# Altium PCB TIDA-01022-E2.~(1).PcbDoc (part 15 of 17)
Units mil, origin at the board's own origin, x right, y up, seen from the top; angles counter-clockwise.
Board outline 6929.13 x 11614.17 mil, 12 copper layers (L1_Top Layer, L2_GND, L3_GND, L4_Signal Layer 1, L5_GND, L6_PWR, L7_GND/PWR, L8_PWR, L9_GND/PWR, L10_Signal Layer 2, L11_GND, L12_Bottom Layer), stack 64.6 mil thick; 1711 components, 1001 nets, 5985 pads, 3200 vias.
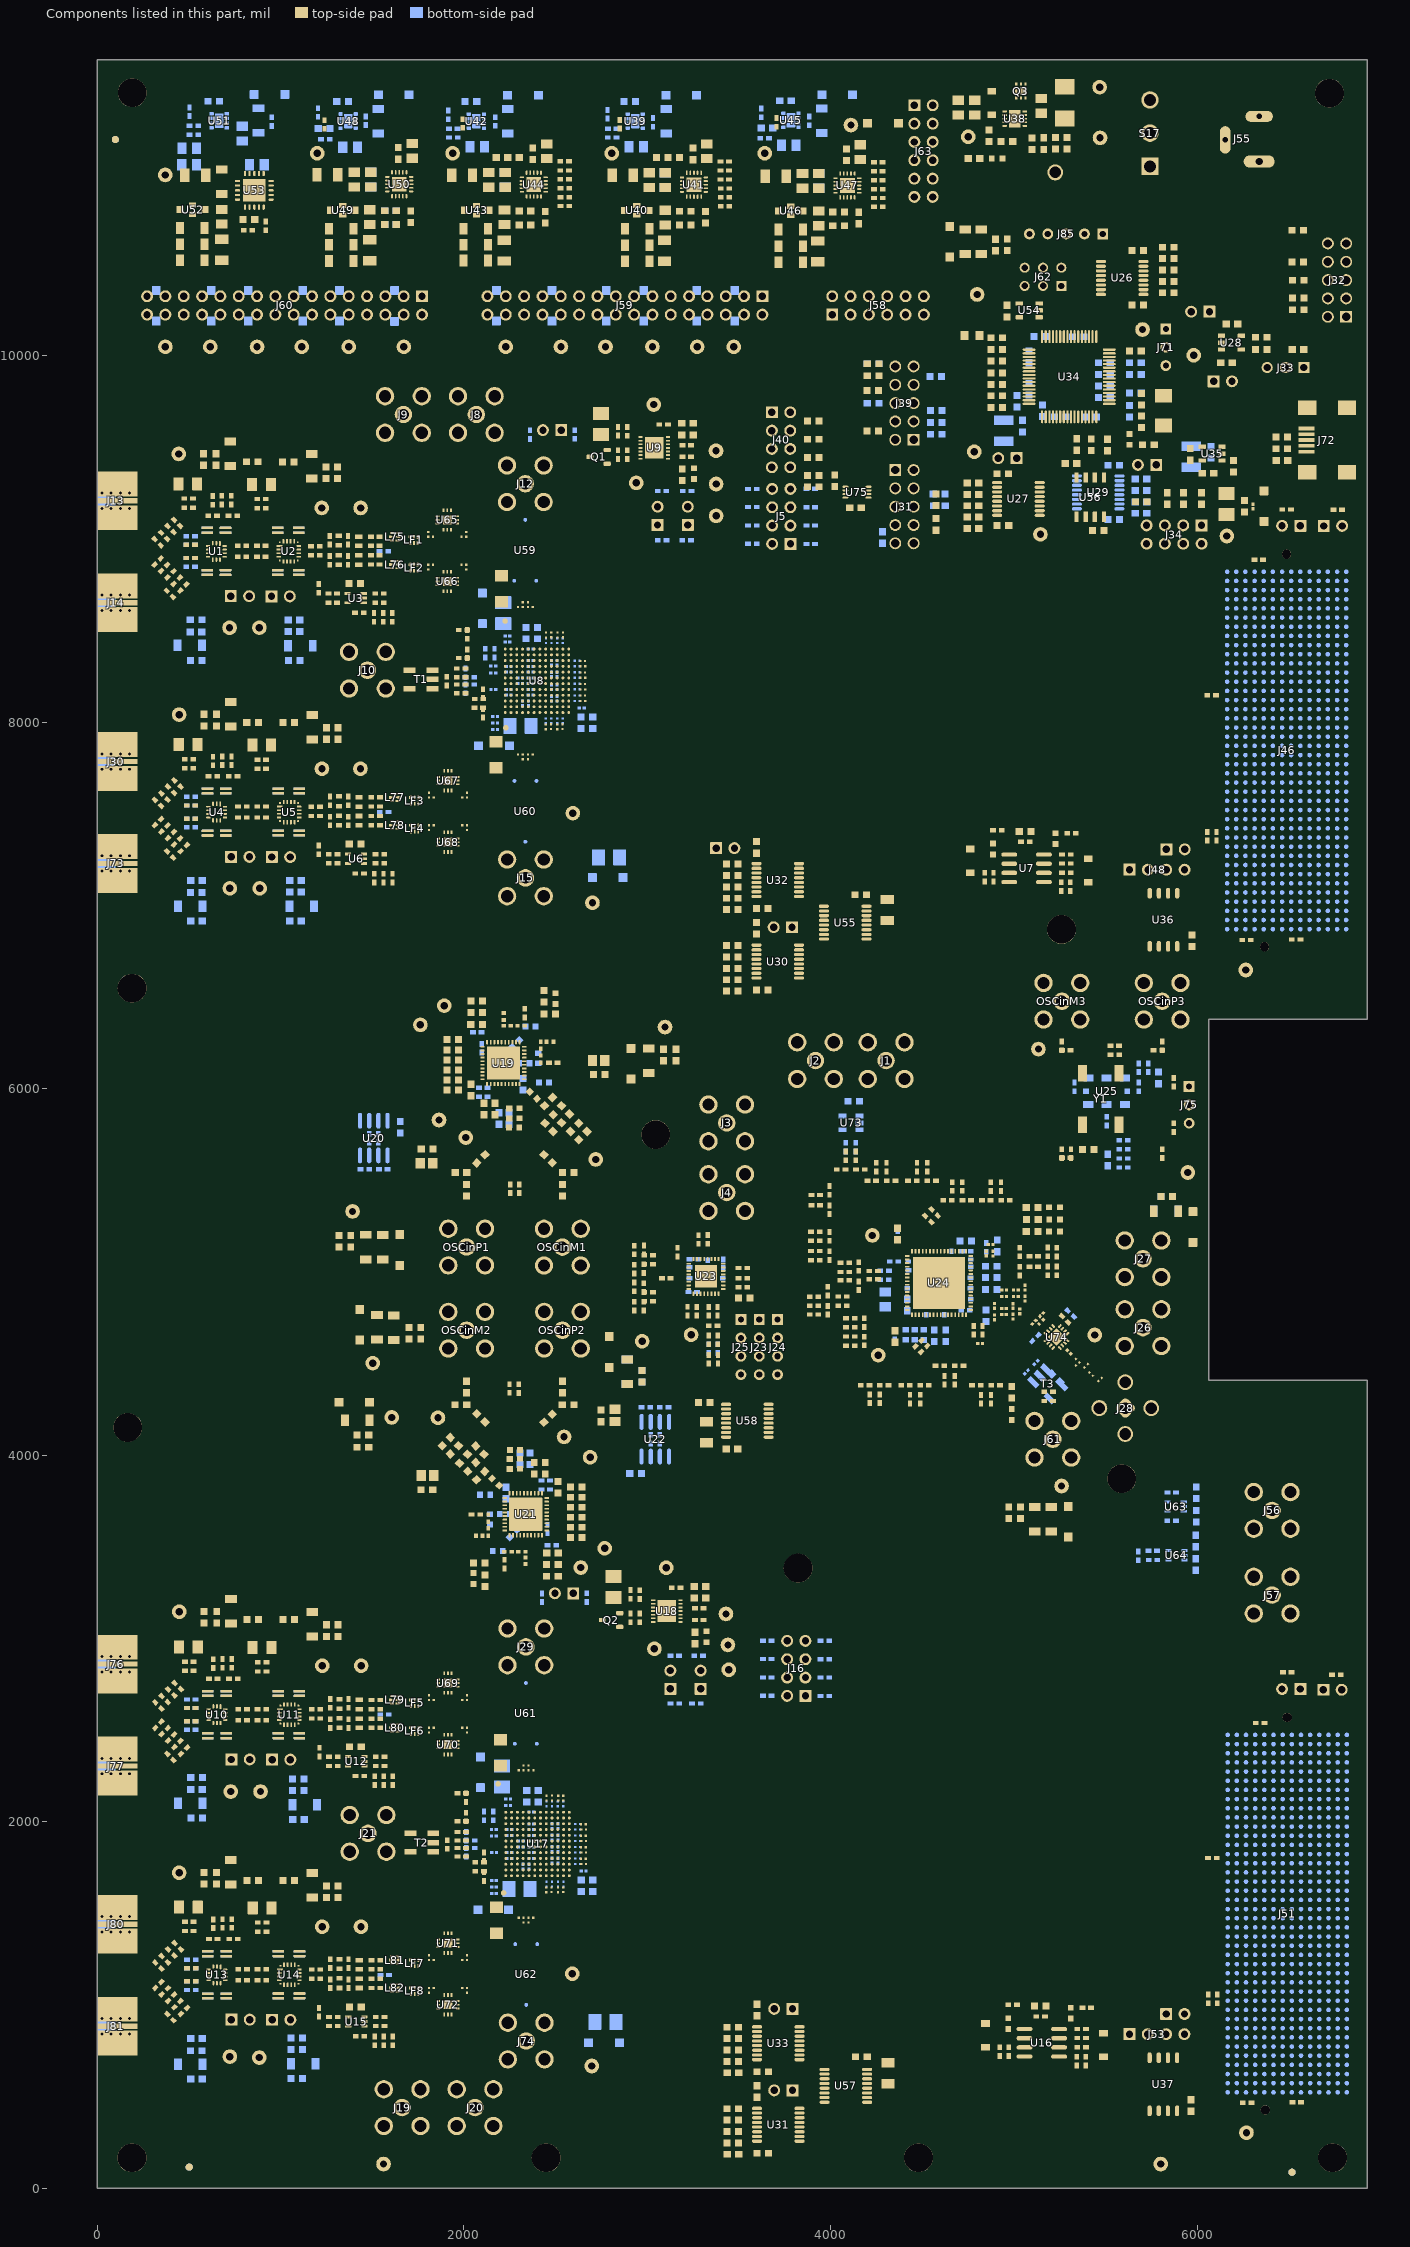
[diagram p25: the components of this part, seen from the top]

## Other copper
L1_Top Layer:
  pour cut-out: 2435,8735 2648,8948 6090,8948 6863,8948 6896,8915 6896,6768 6852,6724 6117,6724 6078,6763 6078,7391 2786,7391 2435,7742
  pour cut-out: 2410.33,2361 2651.33,2602 6866.33,2602 6899.33,2569 6899.33,422 6855.33,378 6120.33,378 6081.33,417 6081.33,1045 2789.33,1045 2410.33,1424
  pour cut-out: 2330.03,8387.72 ccw(c2336.86,8387.72) 2332.03,8382.89 ccw(c2339.27,8390.14) 2339.27,8379.89 2356.37,8379.89 ccw(c2356.37,8393.55) 2366.03,8383.89 ccw(c2358.78,8391.14) 2369.03,8391.14 2369.03,8405.24 ccw(c2355.37,8405.24) 2365.03,8414.89 ccw(c2360.2,8410.06) 2360.2,8416.89 2343.1,8416.89 ccw(c2343.1,8399.82) 2331.03,8411.89 ccw(c2333.44,8409.48) 2330.03,8409.48
  pour cut-out: 2298.53,8387.72 ccw(c2305.36,8387.72) 2300.53,8382.89 ccw(c2307.77,8390.14) 2307.77,8379.89 2324.87,8379.89 ccw(c2324.87,8393.55) 2334.53,8383.89 ccw(c2327.29,8391.14) 2337.53,8391.14 2337.53,8405.24 ccw(c2323.87,8405.24) 2333.53,8414.89 ccw(c2328.7,8410.06) 2328.7,8416.89 2311.6,8416.89 ccw(c2311.6,8399.82) 2299.53,8411.89 ccw(c2301.94,8409.48) 2298.53,8409.48
  pour cut-out: 2204.04,8356.22 ccw(c2210.87,8356.22) 2206.04,8351.4 ccw(c2213.29,8358.64) 2213.29,8348.4 2230.39,8348.4 ccw(c2230.39,8362.05) 2240.04,8352.4 ccw(c2232.8,8359.64) 2243.04,8359.64 2243.04,8373.74 ccw(c2229.39,8373.74) 2239.04,8383.4 ccw(c2234.21,8378.57) 2234.21,8385.4 2217.11,8385.4 ccw(c2217.11,8368.33) 2205.04,8380.4 ccw(c2207.46,8377.98) 2204.04,8377.98
  pour cut-out: 2204.04,8230.24 ccw(c2210.87,8230.24) 2206.04,8225.41 ccw(c2213.29,8232.65) 2213.29,8222.41 2230.39,8222.41 ccw(c2230.39,8236.07) 2240.04,8226.41 ccw(c2232.8,8233.65) 2243.04,8233.65 2243.04,8247.76 ccw(c2229.39,8247.76) 2239.04,8257.41 ccw(c2234.21,8252.58) 2234.21,8259.41 2217.11,8259.41 ccw(c2217.11,8242.34) 2205.04,8254.41 ccw(c2207.46,8252) 2204.04,8252
  pour cut-out: 2204.04,8198.74 ccw(c2210.87,8198.74) 2206.04,8193.92 ccw(c2213.29,8201.16) 2213.29,8190.92 2230.39,8190.92 ccw(c2230.39,8204.57) 2240.04,8194.92 ccw(c2232.8,8202.16) 2243.04,8202.16 2243.04,8216.26 ccw(c2229.39,8216.26) 2239.04,8225.92 ccw(c2234.21,8221.09) 2234.21,8227.92 2217.11,8227.92 ccw(c2217.11,8210.85) 2205.04,8222.92 ccw(c2207.46,8220.5) 2204.04,8220.5
  pour cut-out: 2204.04,8104.26 ccw(c2210.87,8104.26) 2206.04,8099.43 ccw(c2213.29,8106.67) 2213.29,8096.43 2230.39,8096.43 ccw(c2230.39,8110.08) 2240.04,8100.43 ccw(c2232.8,8107.67) 2243.04,8107.67 2243.04,8121.77 ccw(c2229.39,8121.77) 2239.04,8131.43 ccw(c2234.21,8126.6) 2234.21,8133.43 2217.11,8133.43 ccw(c2217.11,8116.36) 2205.04,8128.43 ccw(c2207.46,8126.01) 2204.04,8126.01
  pour cut-out: 2204.18,8070.2 ccw(c2211.01,8070.2) 2206.18,8065.37 ccw(c2213.43,8072.61) 2213.43,8062.37 2230.53,8062.37 ccw(c2230.53,8076.03) 2240.18,8066.37 ccw(c2232.94,8073.61) 2243.18,8073.61 2243.18,8087.71 ccw(c2229.53,8087.71) 2239.18,8097.37 ccw(c2234.36,8092.54) 2234.36,8099.37 2217.26,8099.37 ccw(c2217.26,8082.3) 2205.18,8094.37 ccw(c2207.6,8091.96) 2204.18,8091.96
  pour cut-out: 2235.54,8104.26 ccw(c2242.37,8104.26) 2237.54,8099.43 ccw(c2244.78,8106.67) 2244.78,8096.43 2261.88,8096.43 ccw(c2261.88,8110.08) 2271.54,8100.43 ccw(c2264.3,8107.67) 2274.54,8107.67 2274.54,8121.77 ccw(c2260.88,8121.77) 2270.54,8131.43 ccw(c2265.71,8126.6) 2265.71,8133.43 2248.61,8133.43 ccw(c2248.61,8116.36) 2236.54,8128.43 ccw(c2238.95,8126.01) 2235.54,8126.01
  pour cut-out: 2267.03,8104.26 ccw(c2273.86,8104.26) 2269.03,8099.43 ccw(c2276.28,8106.67) 2276.28,8096.43 2293.38,8096.43 ccw(c2293.38,8110.08) 2303.03,8100.43 ccw(c2295.79,8107.67) 2306.03,8107.67 2306.03,8121.77 ccw(c2292.38,8121.77) 2302.03,8131.43 ccw(c2297.21,8126.6) 2297.21,8133.43 2280.11,8133.43 ccw(c2280.11,8116.36) 2268.03,8128.43 ccw(c2270.45,8126.01) 2267.03,8126.01
  pour cut-out: 2298.53,8041.26 ccw(c2305.36,8041.26) 2300.53,8036.44 ccw(c2307.77,8043.68) 2307.77,8033.44 2324.87,8033.44 ccw(c2324.87,8047.09) 2334.53,8037.44 ccw(c2327.29,8044.68) 2337.53,8044.68 2337.53,8058.78 ccw(c2323.87,8058.78) 2333.53,8068.44 ccw(c2328.7,8063.61) 2328.7,8070.44 2311.6,8070.44 ccw(c2311.6,8053.36) 2299.53,8065.44 ccw(c2301.94,8063.02) 2298.53,8063.02
  pour cut-out: 2330.03,8041.26 ccw(c2336.86,8041.26) 2332.03,8036.44 ccw(c2339.27,8043.68) 2339.27,8033.44 2356.37,8033.44 ccw(c2356.37,8047.09) 2366.03,8037.44 ccw(c2358.78,8044.68) 2369.03,8044.68 2369.03,8058.78 ccw(c2355.37,8058.78) 2365.03,8068.44 ccw(c2360.2,8063.61) 2360.2,8070.44 2343.1,8070.44 ccw(c2343.1,8053.36) 2331.03,8065.44 ccw(c2333.44,8063.02) 2330.03,8063.02
  pour cut-out: 2425.85,8039.93 ccw(c2432.68,8039.93) 2427.85,8035.1 ccw(c2435.1,8042.34) 2435.1,8032.1 2452.2,8032.1 ccw(c2452.2,8045.75) 2461.85,8036.1 ccw(c2454.61,8043.34) 2464.85,8043.34 2464.85,8057.44 ccw(c2451.2,8057.44) 2460.85,8067.1 ccw(c2456.02,8062.27) 2456.02,8069.1 2438.92,8069.1 ccw(c2438.92,8052.03) 2426.85,8064.1 ccw(c2429.27,8061.68) 2425.85,8061.68
  pour cut-out: 2456.01,8041.26 ccw(c2462.84,8041.26) 2458.01,8036.44 ccw(c2465.25,8043.68) 2465.25,8033.44 2482.35,8033.44 ccw(c2482.35,8047.09) 2492.01,8037.44 ccw(c2484.77,8044.68) 2495.01,8044.68 2495.01,8058.78 ccw(c2481.35,8058.78) 2491.01,8068.44 ccw(c2486.18,8063.61) 2486.18,8070.44 2469.08,8070.44 ccw(c2469.08,8053.36) 2457.01,8065.44 ccw(c2459.43,8063.02) 2456.01,8063.02
  pour cut-out: 2487.51,8041.26 ccw(c2494.34,8041.26) 2489.51,8036.44 ccw(c2496.75,8043.68) 2496.75,8033.44 2513.85,8033.44 ccw(c2513.85,8047.09) 2523.51,8037.44 ccw(c2516.26,8044.68) 2526.51,8044.68 2526.51,8058.78 ccw(c2512.85,8058.78) 2522.51,8068.44 ccw(c2517.68,8063.61) 2517.68,8070.44 2500.58,8070.44 ccw(c2500.58,8053.36) 2488.51,8065.44 ccw(c2490.92,8063.02) 2487.51,8063.02
  pour cut-out: 2519,8041.26 ccw(c2525.83,8041.26) 2521,8036.44 ccw(c2528.25,8043.68) 2528.25,8033.44 2545.35,8033.44 ccw(c2545.35,8047.09) 2555,8037.44 ccw(c2547.76,8044.68) 2558,8044.68 2558,8058.78 ccw(c2544.35,8058.78) 2554,8068.44 ccw(c2549.17,8063.61) 2549.17,8070.44 2532.07,8070.44 ccw(c2532.07,8053.36) 2520,8065.44 ccw(c2522.42,8063.02) 2519,8063.02
  pour cut-out: 2519,8072.76 ccw(c2525.83,8072.76) 2521,8067.93 ccw(c2528.25,8075.17) 2528.25,8064.93 2545.35,8064.93 ccw(c2545.35,8078.59) 2555,8068.93 ccw(c2547.76,8076.17) 2558,8076.17 2558,8090.28 ccw(c2544.35,8090.28) 2554,8099.93 ccw(c2549.17,8095.1) 2549.17,8101.93 2532.07,8101.93 ccw(c2532.07,8084.86) 2520,8096.93 ccw(c2522.42,8094.52) 2519,8094.52
  pour cut-out: 2487.51,8072.76 ccw(c2494.34,8072.76) 2489.51,8067.93 ccw(c2496.76,8075.17) 2496.76,8064.93 2513.86,8064.93 ccw(c2513.86,8078.59) 2523.51,8068.93 ccw(c2516.27,8076.17) 2526.51,8076.17 2526.51,8090.28 ccw(c2512.86,8090.28) 2522.51,8099.93 ccw(c2517.68,8095.1) 2517.68,8101.93 2500.58,8101.93 ccw(c2500.58,8084.86) 2488.51,8096.93 ccw(c2490.93,8094.52) 2487.51,8094.52
  pour cut-out: 2456.01,8072.76 ccw(c2462.84,8072.76) 2458.01,8067.93 ccw(c2465.25,8075.17) 2465.25,8064.93 2482.35,8064.93 ccw(c2482.35,8078.59) 2492.01,8068.93 ccw(c2484.77,8076.17) 2495.01,8076.17 2495.01,8090.28 ccw(c2481.35,8090.28) 2491.01,8099.93 ccw(c2486.18,8095.1) 2486.18,8101.93 2469.08,8101.93 ccw(c2469.08,8084.86) 2457.01,8096.93 ccw(c2459.43,8094.52) 2456.01,8094.52
  pour cut-out: 2424.51,8072.76 ccw(c2431.34,8072.76) 2426.51,8067.93 ccw(c2433.76,8075.17) 2433.76,8064.93 2450.86,8064.93 ccw(c2450.86,8078.59) 2460.51,8068.93 ccw(c2453.27,8076.17) 2463.51,8076.17 2463.51,8090.28 ccw(c2449.86,8090.28) 2459.51,8099.93 ccw(c2454.69,8095.1) 2454.69,8101.93 2437.59,8101.93 ccw(c2437.59,8084.86) 2425.51,8096.93 ccw(c2427.93,8094.52) 2424.51,8094.52
  pour cut-out: 2519,8104.26 ccw(c2525.83,8104.26) 2521,8099.43 ccw(c2528.25,8106.67) 2528.25,8096.43 2545.35,8096.43 ccw(c2545.35,8110.08) 2555,8100.43 ccw(c2547.76,8107.67) 2558,8107.67 2558,8121.77 ccw(c2544.35,8121.77) 2554,8131.43 ccw(c2549.17,8126.6) 2549.17,8133.43 2532.07,8133.43 ccw(c2532.07,8116.36) 2520,8128.43 ccw(c2522.42,8126.01) 2519,8126.01
  pour cut-out: 2550.5,8104.26 ccw(c2557.33,8104.26) 2552.5,8099.43 ccw(c2559.74,8106.67) 2559.74,8096.43 2576.84,8096.43 ccw(c2576.84,8110.08) 2586.5,8100.43 ccw(c2579.26,8107.67) 2589.5,8107.67 2589.5,8121.77 ccw(c2575.84,8121.77) 2585.5,8131.43 ccw(c2580.67,8126.6) 2580.67,8133.43 2563.57,8133.43 ccw(c2563.57,8116.36) 2551.5,8128.43 ccw(c2553.91,8126.01) 2550.5,8126.01
  pour cut-out: 2550.5,8135.75 ccw(c2557.33,8135.75) 2552.5,8130.92 ccw(c2559.74,8138.17) 2559.74,8127.92 2576.84,8127.92 ccw(c2576.84,8141.58) 2586.5,8131.92 ccw(c2579.26,8139.17) 2589.5,8139.17 2589.5,8153.27 ccw(c2575.84,8153.27) 2585.5,8162.92 ccw(c2580.67,8158.1) 2580.67,8164.92 2563.57,8164.92 ccw(c2563.57,8147.85) 2551.5,8159.92 ccw(c2553.91,8157.51) 2550.5,8157.51
  pour cut-out: 2519,8135.75 ccw(c2525.83,8135.75) 2521,8130.92 ccw(c2528.25,8138.17) 2528.25,8127.92 2545.35,8127.92 ccw(c2545.35,8141.58) 2555,8131.92 ccw(c2547.76,8139.17) 2558,8139.17 2558,8153.27 ccw(c2544.35,8153.27) 2554,8162.92 ccw(c2549.17,8158.1) 2549.17,8164.92 2532.07,8164.92 ccw(c2532.07,8147.85) 2520,8159.92 ccw(c2522.42,8157.51) 2519,8157.51
  pour cut-out: 2519,8167.25 ccw(c2525.83,8167.25) 2521,8162.42 ccw(c2528.25,8169.66) 2528.25,8159.42 2545.35,8159.42 ccw(c2545.35,8173.08) 2555,8163.42 ccw(c2547.76,8170.66) 2558,8170.66 2558,8184.76 ccw(c2544.35,8184.76) 2554,8194.42 ccw(c2549.17,8189.59) 2549.17,8196.42 2532.07,8196.42 ccw(c2532.07,8179.35) 2520,8191.42 ccw(c2522.42,8189.01) 2519,8189.01
  pour cut-out: 2550.5,8167.25 ccw(c2557.33,8167.25) 2552.5,8162.42 ccw(c2559.74,8169.66) 2559.74,8159.42 2576.84,8159.42 ccw(c2576.84,8173.08) 2586.5,8163.42 ccw(c2579.26,8170.66) 2589.5,8170.66 2589.5,8184.76 ccw(c2575.84,8184.76) 2585.5,8194.42 ccw(c2580.67,8189.59) 2580.67,8196.42 2563.57,8196.42 ccw(c2563.57,8179.35) 2551.5,8191.42 ccw(c2553.91,8189.01) 2550.5,8189.01
  pour cut-out: 2519,8198.74 ccw(c2525.83,8198.74) 2521,8193.92 ccw(c2528.25,8201.16) 2528.25,8190.92 2545.35,8190.92 ccw(c2545.35,8204.57) 2555,8194.92 ccw(c2547.76,8202.16) 2558,8202.16 2558,8216.26 ccw(c2544.35,8216.26) 2554,8225.92 ccw(c2549.17,8221.09) 2549.17,8227.92 2532.07,8227.92 ccw(c2532.07,8210.85) 2520,8222.92 ccw(c2522.42,8220.5) 2519,8220.5
  pour cut-out: 2550.5,8198.74 ccw(c2557.33,8198.74) 2552.5,8193.92 ccw(c2559.74,8201.16) 2559.74,8190.92 2576.84,8190.92 ccw(c2576.84,8204.57) 2586.5,8194.92 ccw(c2579.26,8202.16) 2589.5,8202.16 2589.5,8216.26 ccw(c2575.84,8216.26) 2585.5,8225.92 ccw(c2580.67,8221.09) 2580.67,8227.92 2563.57,8227.92 ccw(c2563.57,8210.85) 2551.5,8222.92 ccw(c2553.91,8220.5) 2550.5,8220.5
  pour cut-out: 2519,8230.24 ccw(c2525.83,8230.24) 2521,8225.41 ccw(c2528.25,8232.65) 2528.25,8222.41 2545.35,8222.41 ccw(c2545.35,8236.07) 2555,8226.41 ccw(c2547.76,8233.65) 2558,8233.65 2558,8247.75 ccw(c2544.35,8247.75) 2554,8257.41 ccw(c2549.17,8252.58) 2549.17,8259.41 2532.07,8259.41 ccw(c2532.07,8242.34) 2520,8254.41 ccw(c2522.42,8251.99) 2519,8251.99
  pour cut-out: 2550.5,8230.24 ccw(c2557.33,8230.24) 2552.5,8225.41 ccw(c2559.74,8232.65) 2559.74,8222.41 2576.84,8222.41 ccw(c2576.84,8236.07) 2586.5,8226.41 ccw(c2579.26,8233.65) 2589.5,8233.65 2589.5,8247.76 ccw(c2575.84,8247.76) 2585.5,8257.41 ccw(c2580.67,8252.58) 2580.67,8259.41 2563.57,8259.41 ccw(c2563.57,8242.34) 2551.5,8254.41 ccw(c2553.91,8252) 2550.5,8252
  pour cut-out: 2550.5,8261.74 ccw(c2557.33,8261.74) 2552.5,8256.91 ccw(c2559.74,8264.15) 2559.74,8253.91 2576.84,8253.91 ccw(c2576.84,8267.57) 2586.5,8257.91 ccw(c2579.26,8265.15) 2589.5,8265.15 2589.5,8279.25 ccw(c2575.84,8279.25) 2585.5,8288.91 ccw(c2580.67,8284.08) 2580.67,8290.91 2563.57,8290.91 ccw(c2563.57,8273.84) 2551.5,8285.91 ccw(c2553.91,8283.49) 2550.5,8283.49
  pour cut-out: 2519,8261.74 ccw(c2525.83,8261.74) 2521,8256.91 ccw(c2528.25,8264.15) 2528.25,8253.91 2545.35,8253.91 ccw(c2545.35,8267.57) 2555,8257.91 ccw(c2547.76,8265.15) 2558,8265.15 2558,8279.25 ccw(c2544.35,8279.25) 2554,8288.91 ccw(c2549.17,8284.08) 2549.17,8290.91 2532.07,8290.91 ccw(c2532.07,8273.84) 2520,8285.91 ccw(c2522.42,8283.49) 2519,8283.49
  pour cut-out: 2519,8293.23 ccw(c2525.83,8293.23) 2521,8288.4 ccw(c2528.25,8295.65) 2528.25,8285.4 2545.35,8285.4 ccw(c2545.35,8299.06) 2555,8289.4 ccw(c2547.76,8296.65) 2558,8296.65 2558,8310.75 ccw(c2544.35,8310.75) 2554,8320.4 ccw(c2549.17,8315.58) 2549.17,8322.4 2532.07,8322.4 ccw(c2532.07,8305.33) 2520,8317.4 ccw(c2522.42,8314.99) 2519,8314.99
  pour cut-out: 2550.5,8293.23 ccw(c2557.33,8293.23) 2552.5,8288.4 ccw(c2559.74,8295.65) 2559.74,8285.4 2576.84,8285.4 ccw(c2576.84,8299.06) 2586.5,8289.4 ccw(c2579.26,8296.65) 2589.5,8296.65 2589.5,8310.75 ccw(c2575.84,8310.75) 2585.5,8320.4 ccw(c2580.67,8315.58) 2580.67,8322.4 2563.57,8322.4 ccw(c2563.57,8305.33) 2551.5,8317.4 ccw(c2553.91,8314.99) 2550.5,8314.99
  pour cut-out: 2519,8324.73 ccw(c2525.83,8324.73) 2521,8319.9 ccw(c2528.25,8327.14) 2528.25,8316.9 2545.35,8316.9 ccw(c2545.35,8330.56) 2555,8320.9 ccw(c2547.76,8328.14) 2558,8328.14 2558,8342.24 ccw(c2544.35,8342.24) 2554,8351.9 ccw(c2549.17,8347.07) 2549.17,8353.9 2532.07,8353.9 ccw(c2532.07,8336.83) 2520,8348.9 ccw(c2522.42,8346.49) 2519,8346.49
  pour cut-out: 2550.5,8324.73 ccw(c2557.33,8324.73) 2552.5,8319.9 ccw(c2559.74,8327.14) 2559.74,8316.9 2576.84,8316.9 ccw(c2576.84,8330.56) 2586.5,8320.9 ccw(c2579.26,8328.14) 2589.5,8328.14 2589.5,8342.24 ccw(c2575.84,8342.24) 2585.5,8351.9 ccw(c2580.67,8347.07) 2580.67,8353.9 2563.57,8353.9 ccw(c2563.57,8336.83) 2551.5,8348.9 ccw(c2553.91,8346.49) 2550.5,8346.49
  pour cut-out: 2425.59,8388.8 ccw(c2432.42,8388.8) 2427.59,8383.97 ccw(c2434.84,8391.21) 2434.84,8380.97 2451.94,8380.97 ccw(c2451.94,8394.63) 2461.59,8384.97 ccw(c2454.35,8392.21) 2464.59,8392.21 2464.59,8406.31 ccw(c2450.94,8406.31) 2460.59,8415.97 ccw(c2455.76,8411.14) 2455.77,8417.97 2438.66,8417.97 ccw(c2438.66,8400.9) 2426.59,8412.97 ccw(c2429.01,8410.56) 2425.59,8410.56
  pour cut-out: 2424.51,8356.22 ccw(c2431.34,8356.22) 2426.51,8351.4 ccw(c2433.76,8358.64) 2433.76,8348.4 2450.86,8348.4 ccw(c2450.86,8362.05) 2460.51,8352.4 ccw(c2453.27,8359.64) 2463.51,8359.64 2463.51,8373.74 ccw(c2449.86,8373.74) 2459.51,8383.4 ccw(c2454.69,8378.57) 2454.69,8385.4 2437.59,8385.4 ccw(c2437.59,8368.33) 2425.51,8380.4 ccw(c2427.93,8377.98) 2424.51,8377.98
  pour cut-out: 2454.67,8389.06 ccw(c2461.5,8389.06) 2456.67,8384.23 ccw(c2463.92,8391.47) 2463.92,8381.23 2481.02,8381.23 ccw(c2481.02,8394.89) 2490.67,8385.23 ccw(c2483.43,8392.47) 2493.67,8392.47 2493.67,8406.57 ccw(c2480.02,8406.57) 2489.67,8416.23 ccw(c2484.84,8411.4) 2484.84,8418.23 2467.74,8418.23 ccw(c2467.74,8401.16) 2455.67,8413.23 ccw(c2458.09,8410.82) 2454.67,8410.82
  pour cut-out: 2456.01,8356.22 ccw(c2462.84,8356.22) 2458.01,8351.4 ccw(c2465.25,8358.64) 2465.25,8348.4 2482.35,8348.4 ccw(c2482.35,8362.05) 2492.01,8352.4 ccw(c2484.77,8359.64) 2495.01,8359.64 2495.01,8373.74 ccw(c2481.35,8373.74) 2491.01,8383.4 ccw(c2486.18,8378.57) 2486.18,8385.4 2469.08,8385.4 ccw(c2469.08,8368.33) 2457.01,8380.4 ccw(c2459.43,8377.98) 2456.01,8377.98
  pour cut-out: 2487.51,8387.72 ccw(c2494.34,8387.72) 2489.51,8382.89 ccw(c2496.75,8390.14) 2496.75,8379.89 2513.85,8379.89 ccw(c2513.85,8393.55) 2523.51,8383.89 ccw(c2516.26,8391.14) 2526.51,8391.14 2526.51,8405.24 ccw(c2512.85,8405.24) 2522.51,8414.89 ccw(c2517.68,8410.06) 2517.68,8416.89 2500.58,8416.89 ccw(c2500.58,8399.82) 2488.51,8411.89 ccw(c2490.92,8409.48) 2487.51,8409.48
  pour cut-out: 2487.51,8356.22 ccw(c2494.34,8356.22) 2489.51,8351.4 ccw(c2496.75,8358.64) 2496.75,8348.4 2513.85,8348.4 ccw(c2513.85,8362.05) 2523.51,8352.4 ccw(c2516.26,8359.64) 2526.51,8359.64 2526.51,8373.74 ccw(c2512.85,8373.74) 2522.51,8383.4 ccw(c2517.68,8378.57) 2517.68,8385.4 2500.58,8385.4 ccw(c2500.58,8368.33) 2488.51,8380.4 ccw(c2490.92,8377.98) 2487.51,8377.98
  pour cut-out: 2517.66,8389.06 ccw(c2524.49,8389.06) 2519.66,8384.23 ccw(c2526.91,8391.47) 2526.91,8381.23 2544.01,8381.23 ccw(c2544.01,8394.89) 2553.66,8385.23 ccw(c2546.42,8392.47) 2556.66,8392.47 2556.66,8406.57 ccw(c2543.01,8406.57) 2552.66,8416.23 ccw(c2547.84,8411.4) 2547.84,8418.23 2530.74,8418.23 ccw(c2530.74,8401.16) 2518.66,8413.23 ccw(c2521.08,8410.82) 2517.66,8410.82
  pour cut-out: 2519,8356.22 ccw(c2525.83,8356.22) 2521,8351.4 ccw(c2528.25,8358.64) 2528.25,8348.4 2545.35,8348.4 ccw(c2545.35,8362.05) 2555,8352.4 ccw(c2547.76,8359.64) 2558,8359.64 2558,8373.74 ccw(c2544.35,8373.74) 2554,8383.4 ccw(c2549.17,8378.57) 2549.17,8385.4 2532.07,8385.4 ccw(c2532.07,8368.33) 2520,8380.4 ccw(c2522.42,8377.98) 2519,8377.98
  pour cut-out: 2207.37,2010.23 ccw(c2214.2,2010.23) 2209.37,2005.4 ccw(c2216.62,2012.64) 2216.62,2002.4 2233.72,2002.4 ccw(c2233.72,2016.06) 2243.37,2006.4 ccw(c2236.13,2013.64) 2246.37,2013.64 2246.37,2027.74 ccw(c2232.72,2027.74) 2242.37,2037.4 ccw(c2237.54,2032.57) 2237.54,2039.4 2220.44,2039.4 ccw(c2220.44,2022.33) 2208.37,2034.4 ccw(c2210.79,2031.99) 2207.37,2031.99
  pour cut-out: 2207.37,1978.73 ccw(c2214.2,1978.73) 2209.37,1973.9 ccw(c2216.62,1981.15) 2216.62,1970.9 2233.72,1970.9 ccw(c2233.72,1984.56) 2243.37,1974.9 ccw(c2236.13,1982.15) 2246.37,1982.15 2246.37,1996.25 ccw(c2232.72,1996.25) 2242.37,2005.9 ccw(c2237.54,2001.08) 2237.54,2007.9 2220.44,2007.9 ccw(c2220.44,1990.83) 2208.37,2002.9 ccw(c2210.79,2000.49) 2207.37,2000.49
  pour cut-out: 2207.37,1884.24 ccw(c2214.2,1884.24) 2209.37,1879.42 ccw(c2216.62,1886.66) 2216.62,1876.42 2233.72,1876.42 ccw(c2233.72,1890.07) 2243.37,1880.42 ccw(c2236.13,1887.66) 2246.37,1887.66 2246.37,1901.76 ccw(c2232.72,1901.76) 2242.37,1911.42 ccw(c2237.54,1906.59) 2237.54,1913.42 2220.44,1913.42 ccw(c2220.44,1896.35) 2208.37,1908.42 ccw(c2210.79,1906) 2207.37,1906
  pour cut-out: 2207.37,1852.75 ccw(c2214.2,1852.75) 2209.37,1847.92 ccw(c2216.62,1855.16) 2216.62,1844.92 2233.72,1844.92 ccw(c2233.72,1858.58) 2243.37,1848.92 ccw(c2236.13,1856.16) 2246.37,1856.16 2246.37,1870.26 ccw(c2232.72,1870.26) 2242.37,1879.92 ccw(c2237.54,1875.09) 2237.54,1881.92 2220.44,1881.92 ccw(c2220.44,1864.85) 2208.37,1876.92 ccw(c2210.79,1874.51) 2207.37,1874.51
  pour cut-out: 2207.37,1758.26 ccw(c2214.2,1758.26) 2209.37,1753.43 ccw(c2216.62,1760.67) 2216.62,1750.43 2233.72,1750.43 ccw(c2233.72,1764.09) 2243.37,1754.43 ccw(c2236.13,1761.67) 2246.37,1761.67 2246.37,1775.77 ccw(c2232.72,1775.77) 2242.37,1785.43 ccw(c2237.54,1780.6) 2237.54,1787.43 2220.44,1787.43 ccw(c2220.44,1770.36) 2208.37,1782.43 ccw(c2210.79,1780.02) 2207.37,1780.02
  pour cut-out: 2207.37,1726.76 ccw(c2214.2,1726.76) 2209.37,1721.94 ccw(c2216.62,1729.18) 2216.62,1718.94 2233.72,1718.94 ccw(c2233.72,1732.59) 2243.37,1722.94 ccw(c2236.13,1730.18) 2246.37,1730.18 2246.37,1744.28 ccw(c2232.72,1744.28) 2242.37,1753.94 ccw(c2237.54,1749.11) 2237.54,1755.94 2220.44,1755.94 ccw(c2220.44,1738.86) 2208.37,1750.94 ccw(c2210.79,1748.52) 2207.37,1748.52
  pour cut-out: 2238.87,1758.26 ccw(c2245.7,1758.26) 2240.87,1753.43 ccw(c2248.11,1760.67) 2248.11,1750.43 2265.21,1750.43 ccw(c2265.21,1764.09) 2274.87,1754.43 ccw(c2267.63,1761.67) 2277.87,1761.67 2277.87,1775.77 ccw(c2264.21,1775.77) 2273.87,1785.43 ccw(c2269.04,1780.6) 2269.04,1787.43 2251.94,1787.43 ccw(c2251.94,1770.36) 2239.87,1782.43 ccw(c2242.28,1780.02) 2238.87,1780.02
  pour cut-out: 2270.37,1758.26 ccw(c2277.19,1758.26) 2272.37,1753.43 ccw(c2279.61,1760.67) 2279.61,1750.43 2296.71,1750.43 ccw(c2296.71,1764.09) 2306.37,1754.43 ccw(c2299.12,1761.67) 2309.37,1761.67 2309.37,1775.77 ccw(c2295.71,1775.77) 2305.37,1785.43 ccw(c2300.54,1780.6) 2300.54,1787.43 2283.44,1787.43 ccw(c2283.44,1770.36) 2271.37,1782.43 ccw(c2273.78,1780.02) 2270.37,1780.02
  pour cut-out: 2301.86,1695.27 ccw(c2308.69,1695.27) 2303.86,1690.44 ccw(c2311.1,1697.68) 2311.1,1687.44 2328.2,1687.44 ccw(c2328.2,1701.1) 2337.86,1691.44 ccw(c2330.62,1698.68) 2340.86,1698.68 2340.86,1712.78 ccw(c2327.2,1712.78) 2336.86,1722.44 ccw(c2332.03,1717.61) 2332.03,1724.44 2314.93,1724.44 ccw(c2314.93,1707.37) 2302.86,1719.44 ccw(c2305.28,1717.03) 2301.86,1717.03
  pour cut-out: 2333.36,1695.27 ccw(c2340.19,1695.27) 2335.36,1690.44 ccw(c2342.6,1697.68) 2342.6,1687.44 2359.7,1687.44 ccw(c2359.7,1701.1) 2369.36,1691.44 ccw(c2362.11,1698.68) 2372.36,1698.68 2372.36,1712.78 ccw(c2358.7,1712.78) 2368.36,1722.44 ccw(c2363.53,1717.61) 2363.53,1724.44 2346.43,1724.44 ccw(c2346.43,1707.37) 2334.36,1719.44 ccw(c2336.77,1717.03) 2333.36,1717.03
  pour cut-out: 2427.85,1695.27 ccw(c2434.67,1695.27) 2429.85,1690.44 ccw(c2437.09,1697.68) 2437.09,1687.44 2454.19,1687.44 ccw(c2454.19,1701.1) 2463.85,1691.44 ccw(c2456.6,1698.68) 2466.85,1698.68 2466.85,1712.78 ccw(c2453.19,1712.78) 2462.85,1722.44 ccw(c2458.02,1717.61) 2458.02,1724.44 2440.92,1724.44 ccw(c2440.92,1707.37) 2428.85,1719.44 ccw(c2431.26,1717.03) 2427.85,1717.03
  pour cut-out: 2427.85,1726.76 ccw(c2434.68,1726.76) 2429.85,1721.94 ccw(c2437.09,1729.18) 2437.09,1718.94 2454.19,1718.94 ccw(c2454.19,1732.59) 2463.85,1722.94 ccw(c2456.61,1730.18) 2466.85,1730.18 2466.85,1744.28 ccw(c2453.19,1744.28) 2462.85,1753.94 ccw(c2458.02,1749.11) 2458.02,1755.94 2440.92,1755.94 ccw(c2440.92,1738.86) 2428.85,1750.94 ccw(c2431.27,1748.52) 2427.85,1748.52
  pour cut-out: 2459.34,1726.76 ccw(c2466.17,1726.76) 2461.34,1721.94 ccw(c2468.58,1729.18) 2468.58,1718.94 2485.68,1718.94 ccw(c2485.68,1732.59) 2495.34,1722.94 ccw(c2488.1,1730.18) 2498.34,1730.18 2498.34,1744.28 ccw(c2484.68,1744.28) 2494.34,1753.94 ccw(c2489.51,1749.11) 2489.51,1755.94 2472.41,1755.94 ccw(c2472.41,1738.86) 2460.34,1750.94 ccw(c2462.76,1748.52) 2459.34,1748.52
  pour cut-out: 2459.34,1695.27 ccw(c2466.17,1695.27) 2461.34,1690.44 ccw(c2468.58,1697.68) 2468.58,1687.44 2485.68,1687.44 ccw(c2485.68,1701.1) 2495.34,1691.44 ccw(c2488.1,1698.68) 2498.34,1698.68 2498.34,1712.78 ccw(c2484.68,1712.78) 2494.34,1722.44 ccw(c2489.51,1717.61) 2489.51,1724.44 2472.41,1724.44 ccw(c2472.41,1707.37) 2460.34,1719.44 ccw(c2462.76,1717.03) 2459.34,1717.03
  pour cut-out: 2490.84,1726.76 ccw(c2497.67,1726.76) 2492.84,1721.94 ccw(c2500.08,1729.18) 2500.08,1718.94 2517.18,1718.94 ccw(c2517.18,1732.59) 2526.84,1722.94 ccw(c2519.6,1730.18) 2529.84,1730.18 2529.84,1744.28 ccw(c2516.18,1744.28) 2525.84,1753.94 ccw(c2521.01,1749.11) 2521.01,1755.94 2503.91,1755.94 ccw(c2503.91,1738.86) 2491.84,1750.94 ccw(c2494.25,1748.52) 2490.84,1748.52
  pour cut-out: 2490.84,1695.27 ccw(c2497.67,1695.27) 2492.84,1690.44 ccw(c2500.08,1697.68) 2500.08,1687.44 2517.18,1687.44 ccw(c2517.18,1701.1) 2526.84,1691.44 ccw(c2519.6,1698.68) 2529.84,1698.68 2529.84,1712.78 ccw(c2516.18,1712.78) 2525.84,1722.44 ccw(c2521.01,1717.61) 2521.01,1724.44 2503.91,1724.44 ccw(c2503.91,1707.37) 2491.84,1719.44 ccw(c2494.25,1717.03) 2490.84,1717.03
  pour cut-out: 2522.33,1726.76 ccw(c2529.16,1726.76) 2524.33,1721.94 ccw(c2531.58,1729.18) 2531.58,1718.94 2548.68,1718.94 ccw(c2548.68,1732.59) 2558.33,1722.94 ccw(c2551.09,1730.18) 2561.33,1730.18 2561.33,1744.28 ccw(c2547.68,1744.28) 2557.33,1753.94 ccw(c2552.51,1749.11) 2552.51,1755.94 2535.4,1755.94 ccw(c2535.4,1738.86) 2523.33,1750.94 ccw(c2525.75,1748.52) 2522.33,1748.52
  pour cut-out: 2522.33,1695.27 ccw(c2529.16,1695.27) 2524.33,1690.44 ccw(c2531.58,1697.68) 2531.58,1687.44 2548.68,1687.44 ccw(c2548.68,1701.1) 2558.33,1691.44 ccw(c2551.09,1698.68) 2561.33,1698.68 2561.33,1712.78 ccw(c2547.68,1712.78) 2557.33,1722.44 ccw(c2552.51,1717.61) 2552.51,1724.44 2535.4,1724.44 ccw(c2535.4,1707.37) 2523.33,1719.44 ccw(c2525.75,1717.03) 2522.33,1717.03
  pour cut-out: 2522.33,1758.26 ccw(c2529.16,1758.26) 2524.33,1753.43 ccw(c2531.58,1760.67) 2531.58,1750.43 2548.68,1750.43 ccw(c2548.68,1764.09) 2558.33,1754.43 ccw(c2551.09,1761.67) 2561.33,1761.67 2561.33,1775.77 ccw(c2547.68,1775.77) 2557.33,1785.43 ccw(c2552.51,1780.6) 2552.51,1787.43 2535.4,1787.43 ccw(c2535.4,1770.36) 2523.33,1782.43 ccw(c2525.75,1780.02) 2522.33,1780.02
  pour cut-out: 2553.83,1758.26 ccw(c2560.66,1758.26) 2555.83,1753.43 ccw(c2563.07,1760.67) 2563.07,1750.43 2580.17,1750.43 ccw(c2580.17,1764.09) 2589.83,1754.43 ccw(c2582.59,1761.67) 2592.83,1761.67 2592.83,1775.77 ccw(c2579.17,1775.77) 2588.83,1785.43 ccw(c2584,1780.6) 2584,1787.43 2566.9,1787.43 ccw(c2566.9,1770.36) 2554.83,1782.43 ccw(c2557.24,1780.02) 2553.83,1780.02
  pour cut-out: 2522.33,1978.73 ccw(c2529.16,1978.73) 2524.33,1973.9 ccw(c2531.58,1981.15) 2531.58,1970.9 2548.68,1970.9 ccw(c2548.68,1984.56) 2558.33,1974.9 ccw(c2551.09,1982.15) 2561.33,1982.15 2561.33,1996.25 ccw(c2547.68,1996.25) 2557.33,2005.9 ccw(c2552.51,2001.08) 2552.51,2007.9 2535.4,2007.9 ccw(c2535.4,1990.83) 2523.33,2002.9 ccw(c2525.75,2000.49) 2522.33,2000.49
  pour cut-out: 2553.83,1978.73 ccw(c2560.66,1978.73) 2555.83,1973.9 ccw(c2563.07,1981.15) 2563.07,1970.9 2580.17,1970.9 ccw(c2580.17,1984.56) 2589.83,1974.9 ccw(c2582.59,1982.15) 2592.83,1982.15 2592.83,1996.25 ccw(c2579.17,1996.25) 2588.83,2005.9 ccw(c2584,2001.08) 2584,2007.9 2566.9,2007.9 ccw(c2566.9,1990.83) 2554.83,2002.9 ccw(c2557.24,2000.49) 2553.83,2000.49
  pour cut-out: 2553.83,1947.24 ccw(c2560.66,1947.24) 2555.83,1942.41 ccw(c2563.07,1949.65) 2563.07,1939.41 2580.17,1939.41 ccw(c2580.17,1953.07) 2589.83,1943.41 ccw(c2582.59,1950.65) 2592.83,1950.65 2592.83,1964.75 ccw(c2579.17,1964.75) 2588.83,1974.41 ccw(c2584,1969.58) 2584,1976.41 2566.9,1976.41 ccw(c2566.9,1959.34) 2554.83,1971.41 ccw(c2557.24,1968.99) 2553.83,1968.99
  pour cut-out: 2524.08,1948.98 ccw(c2530.91,1948.98) 2526.08,1944.15 ccw(c2533.33,1951.4) 2533.33,1941.15 2550.43,1941.15 ccw(c2550.43,1954.81) 2560.08,1945.15 ccw(c2552.84,1952.4) 2563.08,1952.4 2563.08,1966.5 ccw(c2549.43,1966.5) 2559.08,1976.15 ccw(c2554.26,1971.33) 2554.26,1978.15 2537.15,1978.15 ccw(c2537.15,1961.08) 2525.08,1973.15 ccw(c2527.5,1970.74) 2524.08,1970.74
  pour cut-out: 2522.33,1915.74 ccw(c2529.16,1915.74) 2524.33,1910.91 ccw(c2531.58,1918.15) 2531.58,1907.91 2548.68,1907.91 ccw(c2548.68,1921.57) 2558.33,1911.91 ccw(c2551.09,1919.15) 2561.33,1919.15 2561.33,1933.26 ccw(c2547.68,1933.26) 2557.33,1942.91 ccw(c2552.51,1938.08) 2552.51,1944.91 2535.4,1944.91 ccw(c2535.4,1927.84) 2523.33,1939.91 ccw(c2525.75,1937.5) 2522.33,1937.5
  pour cut-out: 2553.83,1915.74 ccw(c2560.66,1915.74) 2555.83,1910.91 ccw(c2563.07,1918.15) 2563.07,1907.91 2580.17,1907.91 ccw(c2580.17,1921.57) 2589.83,1911.91 ccw(c2582.59,1919.15) 2592.83,1919.15 2592.83,1933.26 ccw(c2579.17,1933.26) 2588.83,1942.91 ccw(c2584,1938.08) 2584,1944.91 2566.9,1944.91 ccw(c2566.9,1927.84) 2554.83,1939.91 ccw(c2557.24,1937.5) 2553.83,1937.5
  pour cut-out: 2522.33,1884.24 ccw(c2529.16,1884.24) 2524.33,1879.41 ccw(c2531.58,1886.65) 2531.58,1876.41 2548.68,1876.41 ccw(c2548.68,1890.07) 2558.33,1880.41 ccw(c2551.09,1887.65) 2561.33,1887.65 2561.33,1901.76 ccw(c2547.68,1901.76) 2557.33,1911.41 ccw(c2552.51,1906.58) 2552.51,1913.41 2535.4,1913.41 ccw(c2535.4,1896.34) 2523.33,1908.41 ccw(c2525.75,1906) 2522.33,1906
  pour cut-out: 2553.83,1884.24 ccw(c2560.66,1884.24) 2555.83,1879.42 ccw(c2563.07,1886.66) 2563.07,1876.42 2580.17,1876.42 ccw(c2580.17,1890.07) 2589.83,1880.42 ccw(c2582.59,1887.66) 2592.83,1887.66 2592.83,1901.76 ccw(c2579.17,1901.76) 2588.83,1911.42 ccw(c2584,1906.59) 2584,1913.42 2566.9,1913.42 ccw(c2566.9,1896.34) 2554.83,1908.42 ccw(c2557.24,1906) 2553.83,1906
  pour cut-out: 2522.33,1852.75 ccw(c2529.16,1852.75) 2524.33,1847.92 ccw(c2531.58,1855.16) 2531.58,1844.92 2548.68,1844.92 ccw(c2548.68,1858.58) 2558.33,1848.92 ccw(c2551.09,1856.16) 2561.33,1856.16 2561.33,1870.26 ccw(c2547.68,1870.26) 2557.33,1879.92 ccw(c2552.51,1875.09) 2552.51,1881.92 2535.4,1881.92 ccw(c2535.4,1864.85) 2523.33,1876.92 ccw(c2525.75,1874.51) 2522.33,1874.51
  pour cut-out: 2555.99,1850.59 ccw(c2562.82,1850.59) 2557.99,1845.76 ccw(c2565.23,1853.01) 2565.23,1842.76 2582.33,1842.76 ccw(c2582.33,1856.42) 2591.99,1846.76 ccw(c2584.74,1854.01) 2594.99,1854.01 2594.99,1868.11 ccw(c2581.33,1868.11) 2590.99,1877.76 ccw(c2586.16,1872.93) 2586.16,1879.76 2569.06,1879.76 ccw(c2569.06,1862.69) 2556.99,1874.76 ccw(c2559.4,1872.35) 2555.99,1872.35
  pour cut-out: 2524.08,1823 ccw(c2530.91,1823) 2526.08,1818.17 ccw(c2533.33,1825.41) 2533.33,1815.17 2550.43,1815.17 ccw(c2550.43,1828.83) 2560.08,1819.17 ccw(c2552.84,1826.41) 2563.08,1826.41 2563.08,1840.51 ccw(c2549.43,1840.51) 2559.08,1850.17 ccw(c2554.26,1845.34) 2554.26,1852.17 2537.15,1852.17 ccw(c2537.15,1835.1) 2525.08,1847.17 ccw(c2527.5,1844.76) 2524.08,1844.76
  pour cut-out: 2553.83,1821.25 ccw(c2560.66,1821.25) 2555.83,1816.42 ccw(c2563.07,1823.67) 2563.07,1813.42 2580.17,1813.42 ccw(c2580.17,1827.08) 2589.83,1817.42 ccw(c2582.59,1824.67) 2592.83,1824.67 2592.83,1838.77 ccw(c2579.17,1838.77) 2588.83,1848.42 ccw(c2584,1843.6) 2584,1850.42 2566.9,1850.42 ccw(c2566.9,1833.35) 2554.83,1845.42 ccw(c2557.24,1843.01) 2553.83,1843.01
  pour cut-out: 2524.08,1788.01 ccw(c2530.91,1788.01) 2526.08,1783.18 ccw(c2533.33,1790.42) 2533.33,1780.18 2550.43,1780.18 ccw(c2550.43,1793.84) 2560.08,1784.18 ccw(c2552.84,1791.42) 2563.08,1791.42 2563.08,1805.52 ccw(c2549.43,1805.52) 2559.08,1815.18 ccw(c2554.26,1810.35) 2554.26,1817.18 2537.15,1817.18 ccw(c2537.15,1800.11) 2525.08,1812.18 ccw(c2527.5,1809.76) 2524.08,1809.76
  pour cut-out: 2553.83,1789.76 ccw(c2560.66,1789.76) 2555.83,1784.93 ccw(c2563.07,1792.17) 2563.07,1781.93 2580.17,1781.93 ccw(c2580.17,1795.59) 2589.83,1785.93 ccw(c2582.59,1793.17) 2592.83,1793.17 2592.83,1807.27 ccw(c2579.17,1807.27) 2588.83,1816.93 ccw(c2584,1812.1) 2584,1818.93 2566.9,1818.93 ccw(c2566.9,1801.86) 2554.83,1813.93 ccw(c2557.24,1811.51) 2553.83,1811.51
  pour cut-out: 2427.85,2041.72 ccw(c2434.67,2041.72) 2429.85,2036.9 ccw(c2437.09,2044.14) 2437.09,2033.9 2454.19,2033.9 ccw(c2454.19,2047.55) 2463.85,2037.9 ccw(c2456.6,2045.14) 2466.85,2045.14 2466.85,2059.24 ccw(c2453.19,2059.24) 2462.85,2068.9 ccw(c2458.02,2064.07) 2458.02,2070.9 2440.92,2070.9 ccw(c2440.92,2053.83) 2428.85,2065.9 ccw(c2431.26,2063.48) 2427.85,2063.48
  pour cut-out: 2429.11,2011.49 ccw(c2435.93,2011.49) 2431.11,2006.66 ccw(c2438.35,2013.9) 2438.35,2003.66 2455.45,2003.66 ccw(c2455.45,2017.32) 2465.11,2007.66 ccw(c2457.86,2014.9) 2468.11,2014.9 2468.11,2029 ccw(c2454.45,2029) 2464.11,2038.66 ccw(c2459.28,2033.83) 2459.28,2040.66 2442.18,2040.66 ccw(c2442.18,2023.59) 2430.11,2035.66 ccw(c2432.52,2033.25) 2429.11,2033.25
  pour cut-out: 2459.34,2041.72 ccw(c2466.17,2041.72) 2461.34,2036.9 ccw(c2468.58,2044.14) 2468.58,2033.9 2485.68,2033.9 ccw(c2485.68,2047.55) 2495.34,2037.9 ccw(c2488.1,2045.14) 2498.34,2045.14 2498.34,2059.24 ccw(c2484.68,2059.24) 2494.34,2068.9 ccw(c2489.51,2064.07) 2489.51,2070.9 2472.41,2070.9 ccw(c2472.41,2053.83) 2460.34,2065.9 ccw(c2462.76,2063.48) 2459.34,2063.48
  pour cut-out: 2459.34,2010.23 ccw(c2466.17,2010.23) 2461.34,2005.4 ccw(c2468.58,2012.64) 2468.58,2002.4 2485.68,2002.4 ccw(c2485.68,2016.06) 2495.34,2006.4 ccw(c2488.1,2013.64) 2498.34,2013.64 2498.34,2027.74 ccw(c2484.68,2027.74) 2494.34,2037.4 ccw(c2489.51,2032.57) 2489.51,2039.4 2472.41,2039.4 ccw(c2472.41,2022.33) 2460.34,2034.4 ccw(c2462.76,2031.99) 2459.34,2031.99
  pour cut-out: 2490.84,2041.72 ccw(c2497.67,2041.72) 2492.84,2036.9 ccw(c2500.08,2044.14) 2500.08,2033.9 2517.18,2033.9 ccw(c2517.18,2047.55) 2526.84,2037.9 ccw(c2519.6,2045.14) 2529.84,2045.14 2529.84,2059.24 ccw(c2516.18,2059.24) 2525.84,2068.9 ccw(c2521.01,2064.07) 2521.01,2070.9 2503.91,2070.9 ccw(c2503.91,2053.83) 2491.84,2065.9 ccw(c2494.25,2063.48) 2490.84,2063.48
  pour cut-out: 2490.84,2010.23 ccw(c2497.67,2010.23) 2492.84,2005.4 ccw(c2500.08,2012.64) 2500.08,2002.4 2517.18,2002.4 ccw(c2517.18,2016.06) 2526.84,2006.4 ccw(c2519.6,2013.64) 2529.84,2013.64 2529.84,2027.74 ccw(c2516.18,2027.74) 2525.84,2037.4 ccw(c2521.01,2032.57) 2521.01,2039.4 2503.91,2039.4 ccw(c2503.91,2022.33) 2491.84,2034.4 ccw(c2494.25,2031.99) 2490.84,2031.99
  pour cut-out: 2522.33,2010.23 ccw(c2529.16,2010.23) 2524.33,2005.4 ccw(c2531.58,2012.64) 2531.58,2002.4 2548.68,2002.4 ccw(c2548.68,2016.06) 2558.33,2006.4 ccw(c2551.09,2013.64) 2561.33,2013.64 2561.33,2027.74 ccw(c2547.68,2027.74) 2557.33,2037.4 ccw(c2552.51,2032.57) 2552.51,2039.4 2535.4,2039.4 ccw(c2535.4,2022.33) 2523.33,2034.4 ccw(c2525.75,2031.99) 2522.33,2031.99
  pour cut-out: 2522.33,2041.72 ccw(c2529.16,2041.72) 2524.33,2036.9 ccw(c2531.58,2044.14) 2531.58,2033.9 2548.68,2033.9 ccw(c2548.68,2047.55) 2558.33,2037.9 ccw(c2551.09,2045.14) 2561.33,2045.14 2561.33,2059.24 ccw(c2547.68,2059.24) 2557.33,2068.9 ccw(c2552.51,2064.07) 2552.51,2070.9 2535.4,2070.9 ccw(c2535.4,2053.83) 2523.33,2065.9 ccw(c2525.75,2063.48) 2522.33,2063.48
  pour cut-out: 2333.36,2041.72 ccw(c2340.19,2041.72) 2335.36,2036.9 ccw(c2342.6,2044.14) 2342.6,2033.9 2359.7,2033.9 ccw(c2359.7,2047.55) 2369.36,2037.9 ccw(c2362.11,2045.14) 2372.36,2045.14 2372.36,2059.24 ccw(c2358.7,2059.24) 2368.36,2068.9 ccw(c2363.53,2064.07) 2363.53,2070.9 2346.43,2070.9 ccw(c2346.43,2053.83) 2334.36,2065.9 ccw(c2336.77,2063.48) 2333.36,2063.48
  pour cut-out: 2301.86,2041.72 ccw(c2308.69,2041.72) 2303.86,2036.9 ccw(c2311.1,2044.14) 2311.1,2033.9 2328.2,2033.9 ccw(c2328.2,2047.55) 2337.86,2037.9 ccw(c2330.62,2045.14) 2340.86,2045.14 2340.86,2059.24 ccw(c2327.2,2059.24) 2336.86,2068.9 ccw(c2332.03,2064.07) 2332.03,2070.9 2314.93,2070.9 ccw(c2314.93,2053.83) 2302.86,2065.9 ccw(c2305.28,2063.48) 2301.86,2063.48
  pour cut-out: 2204.04,8324.73 ccw(c2210.87,8324.73) 2206.04,8319.9 ccw(c2213.29,8327.14) 2213.29,8316.9 2230.39,8316.9 ccw(c2230.39,8330.56) 2240.04,8320.9 ccw(c2232.8,8328.14) 2243.04,8328.14 2243.04,8342.24 ccw(c2229.39,8342.24) 2239.04,8351.9 ccw(c2234.21,8347.07) 2234.21,8353.9 2217.11,8353.9 ccw(c2217.11,8336.83) 2205.04,8348.9 ccw(c2207.46,8346.49) 2204.04,8346.49
  text "L1_TOP LAYER" at -2294.53,-2305.19 h60
L4_Signal Layer 1:
  text "'.Layer_Name'" at -2294.32,-2310.1 h60
L10_Signal Layer 2:
  text "'.Layer_Name'" at -2296.32,-2321.1 h60
L2_GND:
  pour cut-out: 3201,10291 3194,10298 3194,10422 3560,10788 3560,11330 3525,11330 3525,10804 3165,10444 3165,10291.81 3165.81,10291
  pour cut-out: 2702,10291 2696,10297 2696,11330 2658,11330 2658,10291
  pour cut-out: 1038,10272.51 1038,11352.34 1010,11352.34 1010,10273
  text "'.Layer_Name'" at -2293.32,-2319.1 h60
L5_GND:
  pour cut-out: 1038,10272.51 1038,11352.34 1010,11352.34 1010,10273
  pour cut-out: 2702,10291 2696,10297 2696,11330 2658,11330 2658,10291
  pour cut-out: 3201,10291 3194,10298 3194,10422 3560,10788 3560,11330 3525,11330 3525,10804 3165,10444 3165,10291.81 3165.81,10291
  text "'.Layer_Name'" at -2296.32,-2322.1 h60
L6_PWR:
  text "'.Layer_Name'" at -2296.32,-2322.1 h60
L7_GND/PWR:
  pour cut-out: 1038,10272.51 1038,11352.34 1010,11352.34 1010,10273
  pour cut-out: 2702,10291 2696,10297 2696,11330 2658,11330 2658,10291
  pour cut-out: 3201,10291 3194,10298 3194,10422 3560,10788 3560,11330 3525,11330 3525,10804 3165,10444 3165,10291.81 3165.81,10291
  text "'.Layer_Name'" at -2295.32,-2318.1 h60
L3_GND:
  pour cut-out: 1038,10272.51 1038,11352.34 1010,11352.34 1010,10273
  pour cut-out: 2702,10291 2696,10297 2696,11330 2658,11330 2658,10291
  pour cut-out: 3201,10291 3194,10298 3194,10422 3560,10788 3560,11330 3525,11330 3525,10804 3165,10444 3165,10291.81 3165.81,10291
  text "'.Layer_Name'" at -2294.32,-2314.1 h60
L8_PWR:
  text "'.Layer_Name'" at -2296.32,-2319.1 h60
L9_GND/PWR:
  pour cut-out: 1038,10272.51 1038,11352.34 1010,11352.34 1010,10273
  pour cut-out: 2702,10291 2696,10297 2696,11330 2658,11330 2658,10291
  pour cut-out: 3201,10291 3194,10298 3194,10422 3560,10788 3560,11330 3525,11330 3525,10804 3165,10444 3165,10291.81 3165.81,10291
  text "'.Layer_Name'" at -2295.32,-2320.1 h60
L11_GND:
  pour cut-out: 1038,10272.51 1038,11352.34 1010,11352.34 1010,10273
  pour cut-out: 2702,10291 2696,10297 2696,11330 2658,11330 2658,10291
  pour cut-out: 3201,10291 3194,10298 3194,10422 3560,10788 3560,11330 3525,11330 3525,10804 3165,10444 3165,10291.81 3165.81,10291
  text "'.Layer_Name'" at -2295.32,-2320.1 h60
